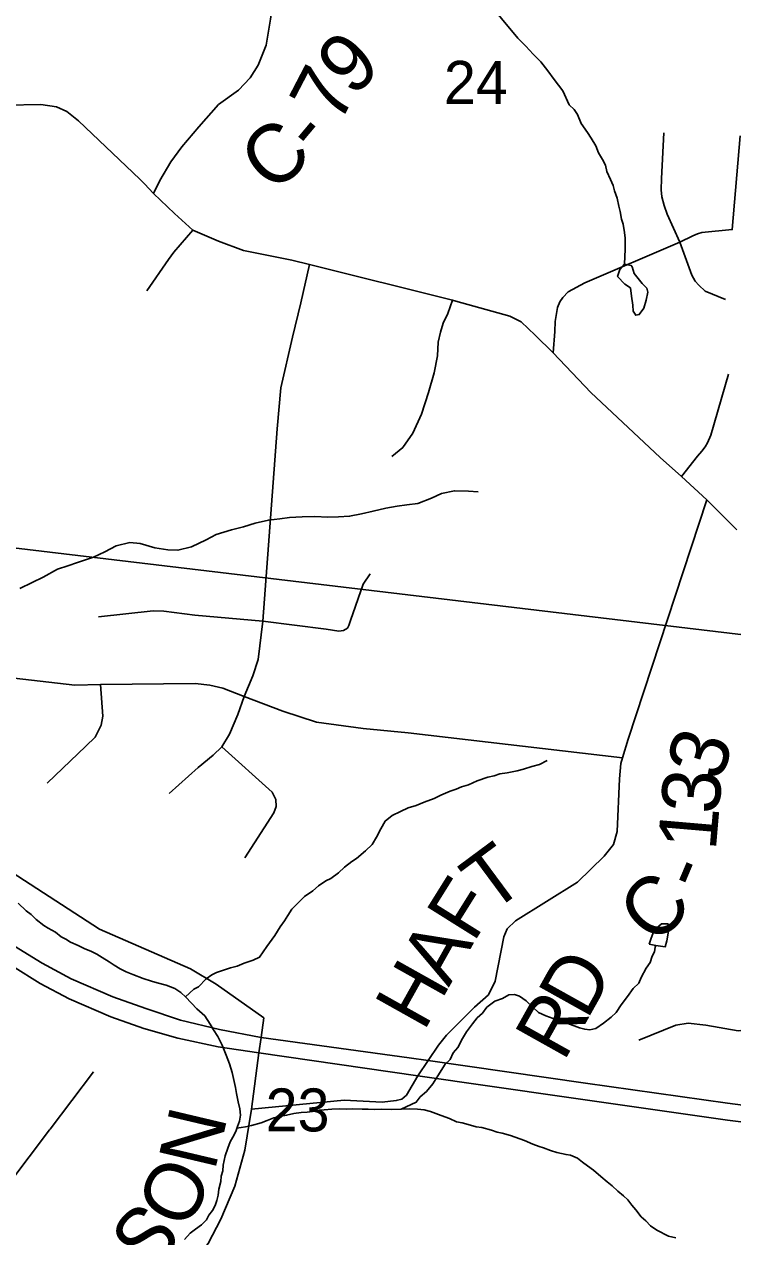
# Model space of a CAD drawing. Extents: x 0 to 34, y 0 to 22.
# Drawn here: x 7.441 to 8.131, y 15.353 to 16.534 of the extents above; entities that cross this region are included whole.
import ezdxf

# ---------------------------------------------------------------- set-up
doc = ezdxf.new("R2010")
doc.units = 0
for name, color, linetype in [('GM_X_County_Road', 7, 'Continuous'), ('GM_X_County_Road_Text', 7, 'Continuous'), ('GM_X_Interstate_Route', 7, 'Continuous'), ('GM_X_Minor_Lake', 7, 'Continuous'), ('GM_X_Minor_River', 7, 'Continuous'), ('GM_X_Section', 7, 'Continuous'), ('GM_X_Section_Text', 7, 'Continuous'), ('GM_X_Township_Road', 7, 'Continuous'), ('GM_X_US_Route', 7, 'Continuous')]:
    doc.layers.add(name, color=color, linetype=linetype)

msp = doc.modelspace()

# ---------------------------------------------------------------- linework, layer by layer
at = {"layer": 'GM_X_County_Road'}
for points in [[(7.5666, 16.3693), (7.5729, 16.382), (7.5835, 16.4001), (7.5945, 16.4148), (7.6108, 16.4342), (7.6302, 16.456), (7.6495, 16.4699), (7.6608, 16.4822), (7.6688, 16.4945), (7.6767, 16.5139), (7.6806, 16.5392), (7.6842, 16.5615), (7.7198, 16.568), (7.7777, 16.5855), (7.783, 16.588), (7.7863, 16.5939), (7.8017, 16.6732), (7.8094, 16.7219), (7.8227, 16.7682), (7.8308, 16.7983), (7.8406, 16.8413), (7.8479, 16.9261), (7.848, 16.9271), (7.8505, 16.9622)], [(7.3896, 16.4548), (7.4569, 16.456), (7.4721, 16.4539), (7.4821, 16.4494), (7.4936, 16.4403), (7.5533, 16.3833)], [(7.5533, 16.3833), (7.5581, 16.3788), (7.5666, 16.3693), (7.5872, 16.35), (7.605, 16.3338), (7.63, 16.323), (7.6545, 16.3138), (7.7015, 16.3045), (7.7187, 16.3002), (7.8583, 16.2653), (7.8613, 16.2646), (7.914, 16.2499), (7.9252, 16.2443), (7.9386, 16.2315), (7.9564, 16.2141), (7.993, 16.1755), (8.0605, 16.1122), (8.0812, 16.0936), (8.1061, 16.071), (8.1353, 16.0417)], [(7.6621, 15.4772), (7.7526, 15.4861), (7.7897, 15.4841), (7.8034, 15.4856), (7.8087, 15.4869), (7.8134, 15.491), (7.8244, 15.5099), (7.8344, 15.5248), (7.8445, 15.5397), (7.8524, 15.5494), (7.8796, 15.5766), (7.8931, 15.5886), (7.8996, 15.6021), (7.9082, 15.6451), (7.9115, 15.6529), (7.9197, 15.6606), (7.9801, 15.6985), (8.006, 15.7239), (8.015, 15.735), (8.0185, 15.7478), (8.0209, 15.799), (8.0221, 15.8141), (8.0238, 15.8195), (8.0294, 15.8378), (8.1061, 16.071)], [(7.4226, 15.7122), (7.514, 15.6525), (7.6028, 15.6139), (7.6279, 15.5989), (7.6743, 15.5662), (7.6716, 15.5472), (7.6695, 15.5323), (7.6621, 15.4772)], [(7.6621, 15.4772), (7.6558, 15.4372), (7.646, 15.4022), (7.6324, 15.37), (7.6199, 15.3465), (7.6053, 15.3283), (7.5857, 15.3085), (7.5712, 15.293), (7.5572, 15.2718), (7.5489, 15.25), (7.5445, 15.2308), (7.5419, 15.2093), (7.5408, 15.1877), (7.5406, 15.1691), (7.5452, 15.1481), (7.5492, 15.1293), (7.5554, 15.1099)]]:
    msp.add_lwpolyline(points, dxfattribs=at)
at = {"layer": 'GM_X_Interstate_Route'}
for points in [[(7.4313, 15.6361), (7.4583, 15.6194), (7.4864, 15.6043), (7.5272, 15.5867), (7.5592, 15.5753), (7.5929, 15.5641), (7.6311, 15.5549), (7.6716, 15.5472), (7.816, 15.5272), (7.8344, 15.5248), (7.9879, 15.5027), (8.1261, 15.4831), (8.241, 15.4682)], [(7.4294, 15.6165), (7.4564, 15.5998), (7.4844, 15.5847), (7.5252, 15.5672), (7.5573, 15.5558), (7.5906, 15.5463), (7.6296, 15.538), (7.6695, 15.5323), (7.8244, 15.5099)], [(7.8244, 15.5099), (7.967, 15.4893), (8.1262, 15.4667), (8.2394, 15.4527), (8.8313, 15.4033), (8.9, 15.3977)]]:
    msp.add_lwpolyline(points, dxfattribs=at)
at = {"layer": 'GM_X_Minor_Lake'}
for points in [[(8.0259, 16.3006), (8.0212, 16.2952), (8.0191, 16.2884), (8.0262, 16.281), (8.0318, 16.2774), (8.0327, 16.2694), (8.034, 16.2606), (8.0342, 16.2546), (8.0368, 16.2507), (8.0402, 16.2514), (8.0445, 16.2577), (8.047, 16.2656), (8.0487, 16.2732), (8.0477, 16.277), (8.0429, 16.2817)], [(8.0429, 16.2817), (8.0352, 16.2914), (8.0334, 16.2979), (8.0323, 16.2991), (8.0259, 16.3006)], [(8.0564, 15.6367), (8.0654, 15.6354), (8.0671, 15.6414), (8.0685, 15.6489), (8.0689, 15.6531), (8.0683, 15.6577), (8.0618, 15.6579), (8.0548, 15.6516), (8.0516, 15.6429), (8.0499, 15.638)], [(8.0499, 15.638), (8.0564, 15.6367)]]:
    msp.add_lwpolyline(points, dxfattribs=at)
at = {"layer": 'GM_X_Minor_River'}
for points in [[(7.8405, 16.6188), (7.9218, 16.5208), (7.9295, 16.5129), (7.9369, 16.505), (7.9442, 16.4976), (7.9511, 16.489), (7.9573, 16.4804), (7.9656, 16.4695), (7.972, 16.4556), (7.9768, 16.4512), (7.98, 16.4462), (7.9835, 16.4377), (7.9897, 16.4287), (7.9933, 16.4233), (7.998, 16.4159), (8.0004, 16.409), (8.0043, 16.4024), (8.0072, 16.397), (8.0085, 16.3909), (8.012, 16.3831), (8.0148, 16.3773), (8.0162, 16.372), (8.0186, 16.3647), (8.0202, 16.357), (8.0216, 16.3517), (8.0228, 16.3444), (8.0246, 16.3394), (8.0258, 16.3314), (8.0264, 16.3257), (8.0264, 16.315), (8.0259, 16.3006)], [(7.4365, 15.9844), (7.4484, 15.9905), (7.4592, 15.9955), (7.4731, 16.0035), (7.4831, 16.0066), (7.4927, 16.0098), (7.5084, 16.015), (7.5192, 16.0204), (7.5303, 16.0262), (7.5437, 16.0292), (7.5536, 16.0285), (7.5679, 16.0243), (7.5807, 16.0221), (7.5906, 16.0218), (7.6036, 16.0252), (7.6182, 16.032), (7.6279, 16.037), (7.6428, 16.0416), (7.6543, 16.0447), (7.6658, 16.0481), (7.6788, 16.0512), (7.6898, 16.0524), (7.6994, 16.0536), (7.7116, 16.0544), (7.7241, 16.0548), (7.7366, 16.0541), (7.7472, 16.0542), (7.7579, 16.055), (7.7694, 16.0573), (7.7808, 16.06), (7.7931, 16.0627), (7.8041, 16.0647), (7.8137, 16.0659), (7.8244, 16.0675), (7.8378, 16.0725), (7.8474, 16.0771), (7.86, 16.0798), (7.8737, 16.0794), (7.8832, 16.0788)], [(7.5978, 15.5868), (7.606, 15.5941), (7.6107, 15.5966), (7.6182, 15.6044), (7.6236, 15.6083), (7.6282, 15.6105), (7.6359, 15.6129), (7.6417, 15.6149), (7.6482, 15.6166), (7.6551, 15.6194), (7.664, 15.6225), (7.6701, 15.6253), (7.6773, 15.6357), (7.6849, 15.6465), (7.6901, 15.655), (7.6945, 15.6606), (7.6977, 15.6658), (7.7014, 15.6721), (7.7092, 15.6798), (7.7139, 15.6846), (7.7221, 15.69), (7.7276, 15.6948), (7.7346, 15.6998), (7.7396, 15.7019), (7.747, 15.7074), (7.7529, 15.7129), (7.7599, 15.7187), (7.7645, 15.7216), (7.7735, 15.7289), (7.7798, 15.7351), (7.7842, 15.7422), (7.7883, 15.7504), (7.7924, 15.7579), (7.7994, 15.7633), (7.8075, 15.7672), (7.8148, 15.7708), (7.8229, 15.7731), (7.8306, 15.7763), (7.8402, 15.7801), (7.8468, 15.7833), (7.856, 15.7872), (7.8618, 15.7889), (7.8668, 15.7914), (7.8737, 15.7934), (7.8822, 15.7973), (7.8925, 15.8007), (7.8987, 15.802), (7.9044, 15.8041), (7.9113, 15.805), (7.9212, 15.807), (7.9274, 15.8086), (7.9354, 15.811), (7.9431, 15.813), (7.9504, 15.817)], [(7.6305, 15.3992), (7.6323, 15.4067), (7.6328, 15.412), (7.6342, 15.4173), (7.6347, 15.4226), (7.6365, 15.4317), (7.6391, 15.4392), (7.6416, 15.4455), (7.644, 15.45), (7.6469, 15.4556), (7.6485, 15.4605), (7.6506, 15.4657), (7.6516, 15.4714), (7.651, 15.4775), (7.6494, 15.4844), (7.6477, 15.4924), (7.6468, 15.4985), (7.6455, 15.5043), (7.6435, 15.5131), (7.6408, 15.5215), (7.6376, 15.53), (7.6338, 15.5396), (7.6295, 15.5481), (7.6252, 15.5547), (7.622, 15.5602), (7.6166, 15.5683), (7.6088, 15.5751), (7.5982, 15.5864), (7.5934, 15.5908), (7.5875, 15.5948), (7.5792, 15.5981), (7.5702, 15.6003), (7.5649, 15.602), (7.5567, 15.6046), (7.5465, 15.6084), (7.5402, 15.6112), (7.5342, 15.6141), (7.5283, 15.6177), (7.5234, 15.6209), (7.5167, 15.625), (7.5115, 15.6282), (7.5063, 15.631), (7.4992, 15.6339), (7.4932, 15.6368), (7.4857, 15.6401), (7.4813, 15.6429), (7.4768, 15.6453), (7.4713, 15.6497), (7.4642, 15.6537), (7.4597, 15.6562), (7.4523, 15.6621), (7.4476, 15.6669), (7.4427, 15.6704), (7.4347, 15.6779)], [(7.808, 15.4774), (7.8229, 15.4841), (7.8268, 15.4893), (7.8327, 15.4944), (7.839, 15.5018), (7.8439, 15.5096), (7.8511, 15.5211), (7.8558, 15.5255), (7.8587, 15.5322), (7.8634, 15.5374), (7.8679, 15.546), (7.8719, 15.5527), (7.8775, 15.5604), (7.8822, 15.5663), (7.8873, 15.5707), (7.8917, 15.5767), (7.8995, 15.5825), (7.9068, 15.5852), (7.913, 15.5885), (7.9187, 15.589), (7.9236, 15.5873), (7.9299, 15.5829), (7.9369, 15.5762), (7.942, 15.5715), (7.9491, 15.5682), (7.9563, 15.5657), (7.9641, 15.5631), (7.9705, 15.5606), (7.9818, 15.5564), (7.987, 15.5551), (7.9919, 15.5546), (7.9977, 15.5559), (8.0054, 15.5609), (8.0129, 15.5668), (8.0176, 15.5715), (8.0224, 15.579), (8.0287, 15.5871), (8.0343, 15.5949), (8.0398, 15.6), (8.0419, 15.6056), (8.0468, 15.6146), (8.0508, 15.6201), (8.0529, 15.6262), (8.0549, 15.6306), (8.0558, 15.6352), (8.0564, 15.6367)], [(7.6479, 15.4587), (7.6565, 15.4602), (7.6622, 15.4612), (7.6718, 15.4639), (7.6776, 15.4663), (7.6841, 15.4687), (7.691, 15.4704), (7.6964, 15.4714), (7.7036, 15.473), (7.7105, 15.4739), (7.7166, 15.4745), (7.7216, 15.4751), (7.7284, 15.4763), (7.733, 15.4766), (7.7406, 15.4774), (7.7478, 15.4776), (7.7547, 15.4773), (7.7611, 15.4775), (7.7702, 15.4772), (7.7759, 15.4773), (7.7824, 15.4771), (7.7885, 15.4773), (7.7983, 15.477), (7.8082, 15.4774), (7.8162, 15.4775), (7.8241, 15.4772), (7.8306, 15.4766), (7.8366, 15.4749), (7.8418, 15.4732), (7.8471, 15.4711), (7.8553, 15.4681), (7.8621, 15.4649), (7.8677, 15.4639), (7.8734, 15.4622), (7.8813, 15.46), (7.8866, 15.4595), (7.8963, 15.4568), (7.9016, 15.4548), (7.9065, 15.4538), (7.9148, 15.4517), (7.9283, 15.4466), (7.9365, 15.4433), (7.9425, 15.4408), (7.947, 15.4395), (7.9537, 15.437), (7.9598, 15.4349), (7.9688, 15.4331), (7.9733, 15.4325), (7.9801, 15.4296), (7.9849, 15.4257), (7.9897, 15.4221), (7.9956, 15.4177), (8.0026, 15.4118), (8.0089, 15.4066), (8.0137, 15.4026), (8.0192, 15.3975), (8.0247, 15.3928), (8.0292, 15.3888), (8.0328, 15.3838), (8.0368, 15.3791), (8.0419, 15.3724), (8.0467, 15.3685), (8.0511, 15.3637), (8.0574, 15.3594), (8.0686, 15.3536), (8.0757, 15.3519)], [(7.5969, 15.3502), (7.6025, 15.3565), (7.6075, 15.3605), (7.6134, 15.3645), (7.6185, 15.3696), (7.6205, 15.3741), (7.6241, 15.3785), (7.6269, 15.3834), (7.6286, 15.3882), (7.6299, 15.3935), (7.6305, 15.3992)]]:
    msp.add_lwpolyline(points, dxfattribs=at)
at = {"layer": 'GM_X_Section'}
for points in [[(7.2711, 17.0443), (8.3778, 16.9409), (8.2891, 15.9218), (7.2064, 16.0507)], [(7.2064, 16.0507), (8.2891, 15.9218), (8.1869, 14.9268), (7.1496, 15.0512)]]:
    msp.add_lwpolyline(points, close=True, dxfattribs=at)
at = {"layer": 'GM_X_Township_Road'}
msp.add_line((7.5815, 16.305), (7.5603, 16.2744), dxfattribs=at)
for points in [[(8.0797, 16.3219), (8.0673, 16.3492), (8.0644, 16.3577), (8.0621, 16.366), (8.0617, 16.3729), (8.0619, 16.3841), (8.0643, 16.4285)], [(8.0797, 16.3219), (8.0925, 16.3281), (8.097, 16.3301), (8.1013, 16.3315), (8.1308, 16.3342), (8.1385, 16.4254)], [(7.605, 16.3338), (7.5866, 16.3123), (7.5815, 16.305)], [(7.9564, 16.2141), (7.9579, 16.235), (7.9583, 16.2448), (7.9604, 16.2582), (7.9629, 16.2638), (7.9657, 16.268), (7.971, 16.2736), (7.9872, 16.2824), (8.0797, 16.3219)], [(8.1242, 16.2661), (8.1044, 16.2741), (8.0982, 16.2799), (8.0947, 16.2838), (8.0913, 16.2899), (8.0797, 16.3219)], [(7.582, 15.7847), (7.6104, 15.81), (7.625, 15.822), (7.6334, 15.8304), (7.6409, 15.8425), (7.6488, 15.8617), (7.6552, 15.8792), (7.6637, 15.8996), (7.6686, 15.9155), (7.6732, 15.9528), (7.6874, 16.1401), (7.6909, 16.18), (7.7022, 16.2295), (7.7104, 16.2629), (7.7187, 16.3002)], [(7.7991, 16.1131), (7.8096, 16.122), (7.8194, 16.136), (7.8281, 16.1545), (7.8346, 16.1754), (7.8403, 16.1945), (7.8436, 16.2112), (7.8442, 16.2246), (7.8466, 16.2344), (7.849, 16.2431), (7.8537, 16.2526), (7.8583, 16.2653)], [(8.0812, 16.0936), (8.097, 16.1136), (8.1012, 16.1183), (8.1043, 16.1225), (8.1068, 16.1264), (8.1098, 16.1339), (8.1271, 16.1935)], [(7.5132, 15.957), (7.5663, 15.9627), (7.5768, 15.9624), (7.6069, 15.9587), (7.6732, 15.9528), (7.735, 15.9449), (7.7474, 15.9431), (7.752, 15.9437), (7.7557, 15.9459), (7.757, 15.9484), (7.7588, 15.9532), (7.7711, 15.9886), (7.7778, 15.9988)], [(8.0238, 15.8195), (7.815, 15.8439), (7.7711, 15.8482), (7.7256, 15.8543), (7.6927, 15.8649), (7.6552, 15.8792), (7.6343, 15.8875), (7.6216, 15.8904), (7.6072, 15.892), (7.5152, 15.8909), (7.4901, 15.8905), (7.4137, 15.899)], [(7.4632, 15.7949), (7.5007, 15.8309), (7.5098, 15.8397), (7.5157, 15.8514), (7.5172, 15.8601), (7.5152, 15.8909)], [(7.6334, 15.8304), (7.6824, 15.7862), (7.6861, 15.779), (7.6863, 15.7723), (7.684, 15.766), (7.6556, 15.7222)], [(8.0399, 15.5444), (8.0758, 15.559), (8.088, 15.5609), (8.1051, 15.559), (8.1365, 15.5537), (8.149, 15.5553), (8.1651, 15.5596), (8.1928, 15.5665), (8.205, 15.5705), (8.2186, 15.5699), (8.232, 15.5683), (8.2514, 15.5662)], [(7.4654, 15.4571), (7.466, 15.4579), (7.5083, 15.5137)], [(7.4044, 15.3767), (7.4056, 15.3783), (7.4654, 15.4571)]]:
    msp.add_lwpolyline(points, dxfattribs=at)
at = {"layer": 'GM_X_US_Route'}
for points in [[(7.4294, 15.6165), (7.4564, 15.5998), (7.4844, 15.5847), (7.5252, 15.5672), (7.5573, 15.5558), (7.5906, 15.5463), (7.6296, 15.538), (7.6695, 15.5323), (7.8244, 15.5099)], [(7.8244, 15.5099), (7.967, 15.4893), (8.1262, 15.4667), (8.2394, 15.4527), (8.8313, 15.4033), (8.9, 15.3977)]]:
    msp.add_lwpolyline(points, dxfattribs=at)

# ---------------------------------------------------------------- texts
at = {"layer": 'GM_X_County_Road_Text'}
for s, rotation, p in [('9', 44.4057, (7.7608, 16.4622)), ('7', 62.4633, (7.7475, 16.435)), ('C', 40.6906, (7.6825, 16.3683)), ('-', 49.9607, (7.7249, 16.4059)), ('3', 72.6969, (8.1197, 15.7954)), ('3', 85.8117, (8.1178, 15.7639)), ('1', 85.0924, (8.1147, 15.7282)), ('T', 36.5363, (7.8951, 15.6669)), ('-', 67.1327, (8.101, 15.6879)), ('F', 57.9699, (7.8786, 15.6385)), ('C', 45.8777, (8.0559, 15.6353)), ('A', 60.6913, (7.8545, 15.5955)), ('D', 60.8693, (7.9893, 15.5633)), ('H', 60.7639, (7.8301, 15.5519)), ('R', 60.7896, (7.9665, 15.5225)), ('N', 76.6956, (7.6264, 15.4161)), ('O', 63.2632, (7.599, 15.3578)), ('S', 45.5636, (7.561, 15.3149))]:
    msp.add_text(s, height=0.0568, rotation=rotation, dxfattribs=at).set_placement(p)
at = {"layer": 'GM_X_Section_Text'}
for s, p in [('24', (7.8498, 16.4567)), ('23', (7.676, 15.4556))]:
    msp.add_text(s, height=0.04186, rotation=0, dxfattribs=at).set_placement(p)

doc.saveas('drawing.dxf')
